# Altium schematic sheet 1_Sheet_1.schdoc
size 599 x 426 mm; Name: A_A2; Symbol: A_A2; Device: A_A2; @Project Name: OAE board 0.2; REV: 1.0; Date: 2023-09-23; Sheet: 1/1; Draw By: intercipere; Company: Your Company; Convert to PCB: yes; Add into BOM: yes; @Page No: 1; @Page Count: 1; @Schematic Name: OAE board 0.4; @Board Name: OAE board 0.4; @Update Date: 2025-04-07; @Create Time: 11:09:19; @Update Time: 13:09:20; @Page Name: Sheet_1; @Create Date: 2025-04-07
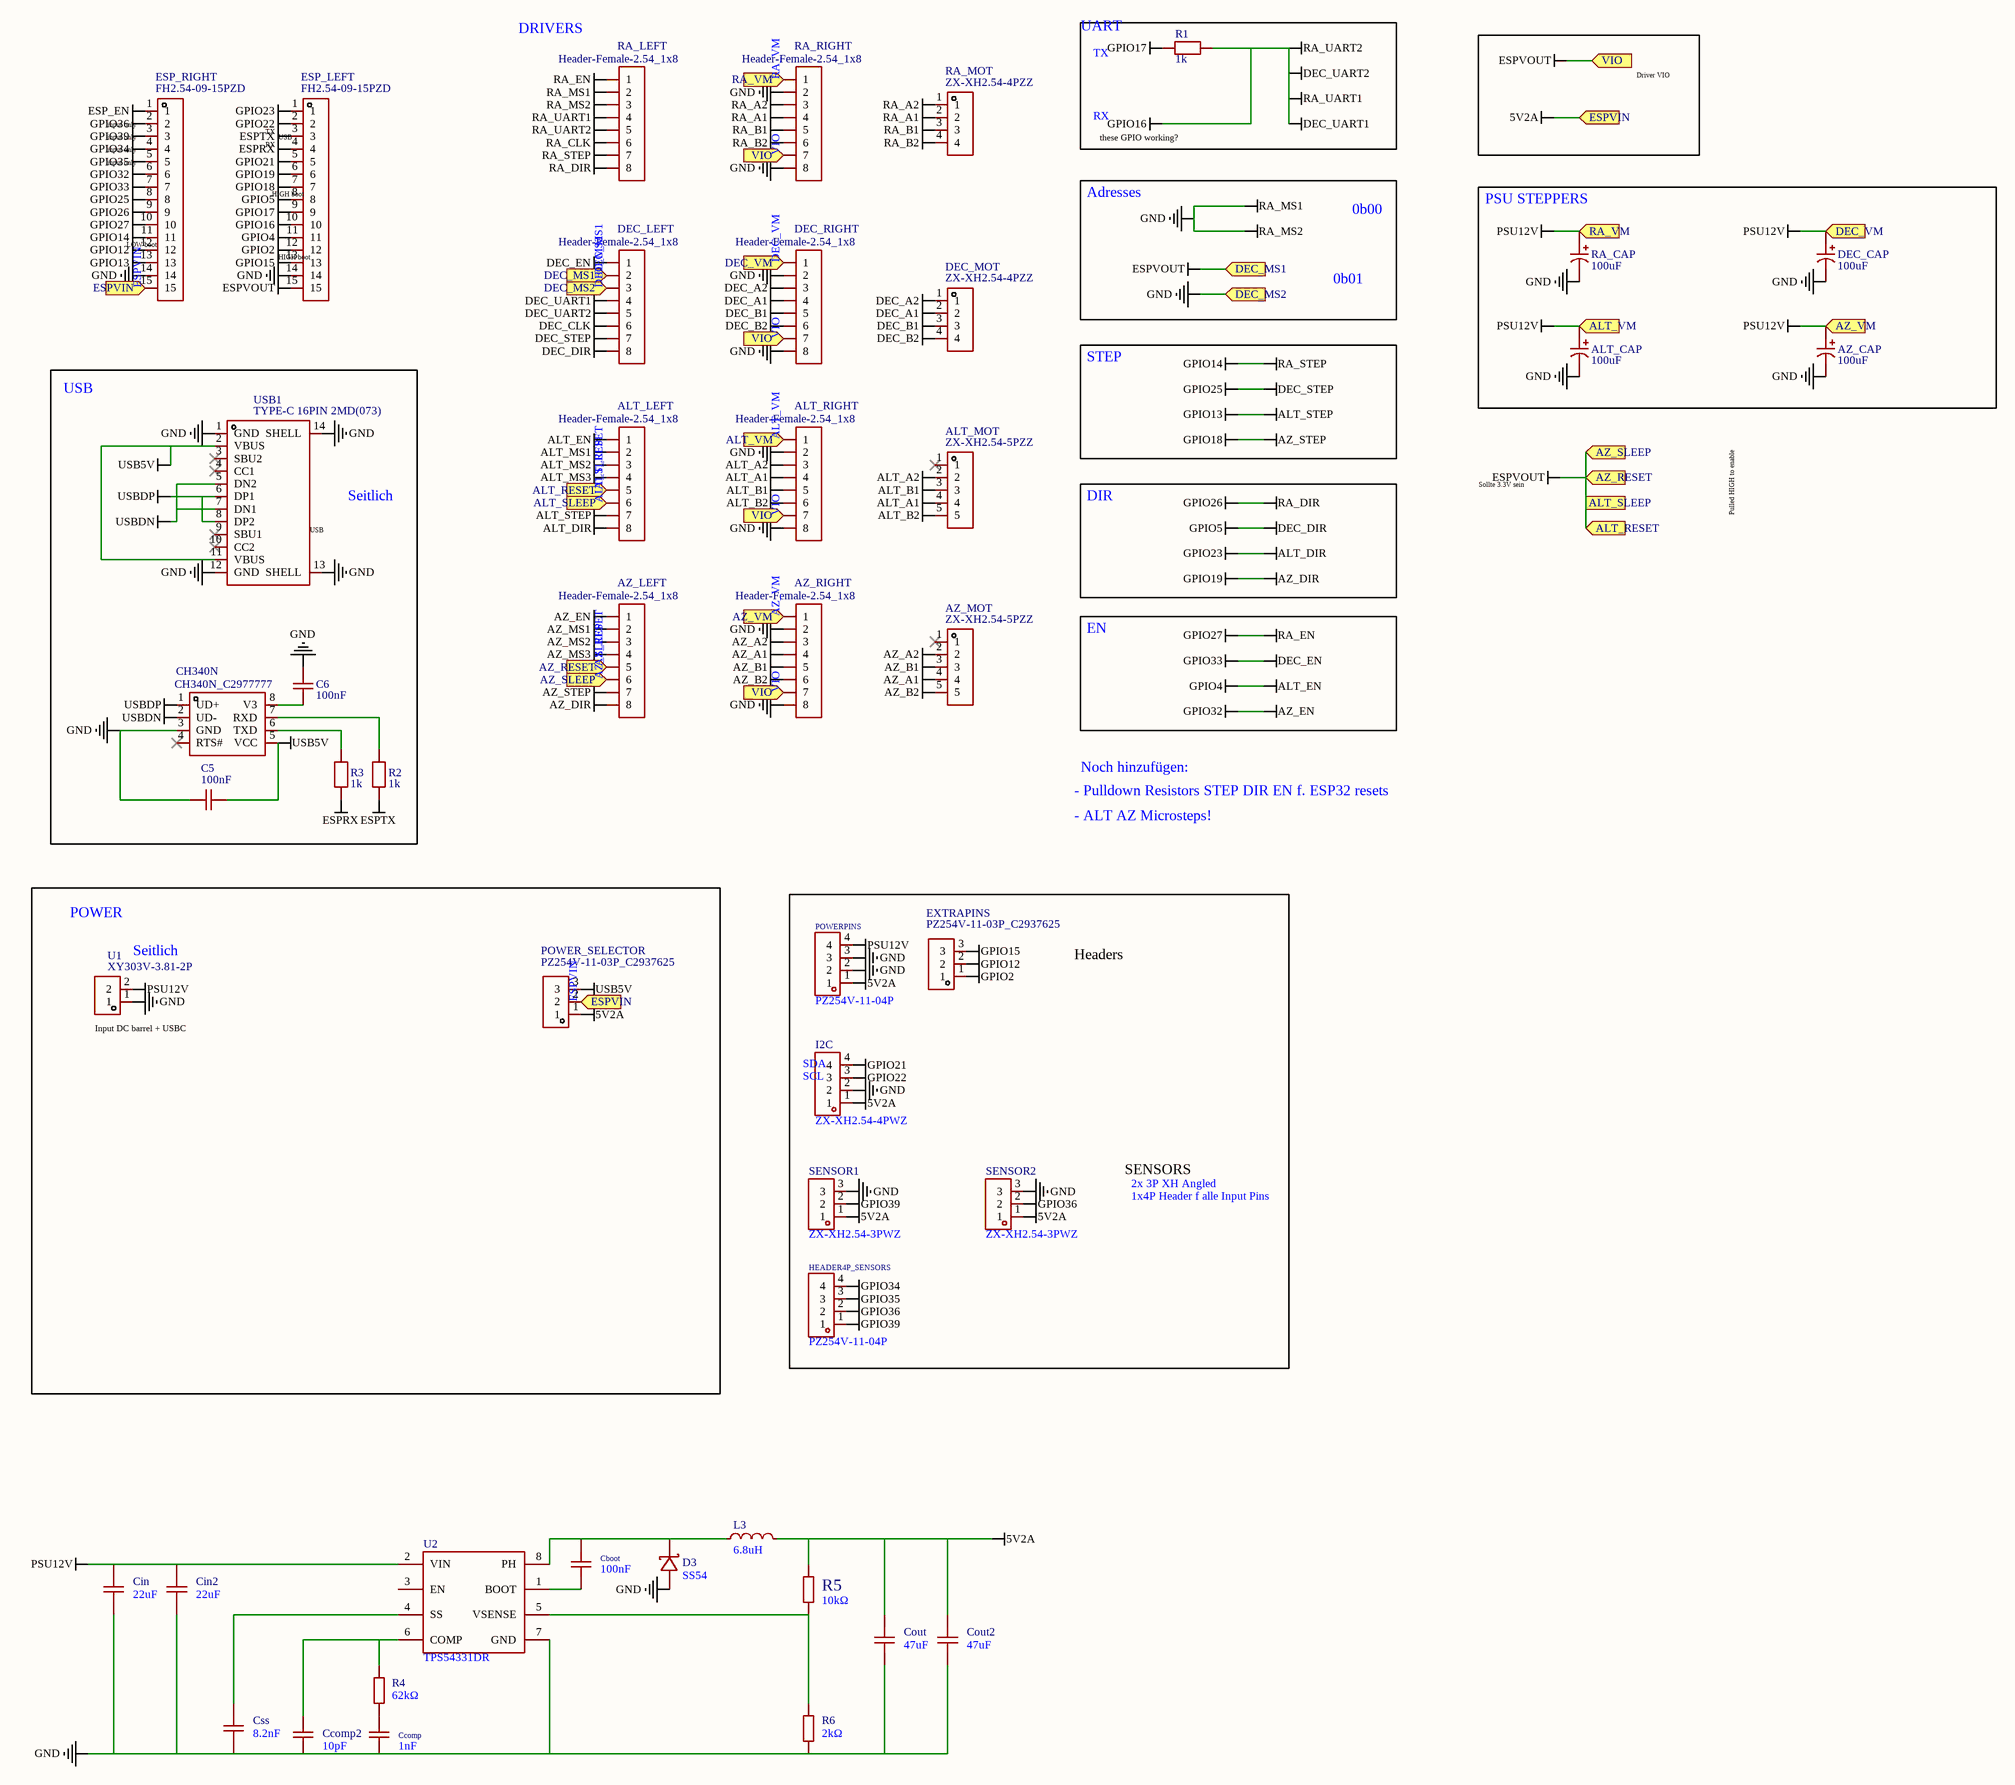
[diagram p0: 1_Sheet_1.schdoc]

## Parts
ALT_CAP  100uF  [CAP-SMD_BD6.3-L6.6-W6.6-LS7.4-FD]
ALT_LEFT  Header-Female-2.54_1x8  [HDR-TH_8P-P2.54-V-F-1]
ALT_MOT  ZX-XH2.54-5PZZ  [CONN-TH_5P-P2.50_ZX-XH2.54-5PZZ]
ALT_RIGHT  Header-Female-2.54_1x8  [HDR-TH_8P-P2.54-V-F-1]
AZ_CAP  100uF  [CAP-SMD_BD6.3-L6.6-W6.6-LS7.4-FD]
AZ_LEFT  Header-Female-2.54_1x8  [HDR-TH_8P-P2.54-V-F-1]
AZ_MOT  ZX-XH2.54-5PZZ  [CONN-TH_5P-P2.50_ZX-XH2.54-5PZZ]
AZ_RIGHT  Header-Female-2.54_1x8  [HDR-TH_8P-P2.54-V-F-1]
C5  100nF  [C0402]
C6  100nF  [C0402]
Cboot  100nF  [C0603]
Ccomp  1nF  [C0603]
Ccomp2  10pF  [C0603]
CH340N  CH340N_C2977777  [SOP-8_L4.9-W3.9-P1.27-LS6.0-BL]
Cin  22uF  [C0805]
Cin2  22uF  [C0805]
Cout  47uF  [C1206]
Cout2  47uF  [C1206]
Css  8.2nF  [C0603]
D3  SS54  [SMA_L4.4-W2.8-LS5.4-R-RD]
DEC_CAP  100uF  [CAP-SMD_BD6.3-L6.6-W6.6-LS7.4-FD]
DEC_LEFT  Header-Female-2.54_1x8  [HDR-TH_8P-P2.54-V-F-1]
DEC_MOT  ZX-XH2.54-4PZZ  [CONN-TH_4P-P2.50_4PIN]
DEC_RIGHT  Header-Female-2.54_1x8  [HDR-TH_8P-P2.54-V-F-1]
ESP_LEFT  FH2.54-09-15PZD  [HDR-TH_15P-P2.54-V-F-1]
ESP_RIGHT  FH2.54-09-15PZD  [HDR-TH_15P-P2.54-V-F-1]
EXTRAPINS  PZ254V-11-03P_C2937625  [HDR-TH_3P-P2.54-V-M]
HEADER4P_SENSORS  PZ254V-11-04P  [HDR-TH_4P-P2.54-V-M]
I2C  ZX-XH2.54-4PWZ  [CONN-TH_4P-P2.50_ZX-XH2.54-4PWZ]
L3  6.8uH  [IND-SMD_L2.0-W1.3]
POWER_SELECTOR  PZ254V-11-03P_C2937625  [HDR-TH_3P-P2.54-V-M]
POWERPINS  PZ254V-11-04P  [HDR-TH_4P-P2.54-V-M]
R1  1k  [R0603]
R2  1k  [R0603]
R3  1k  [R0603]
R4  62kΩ  [R0805]
R5  10kΩ  [R0603]
R6  2kΩ  [R0603]
RA_CAP  100uF  [CAP-SMD_BD6.3-L6.6-W6.6-LS7.4-FD]
RA_LEFT  Header-Female-2.54_1x8  [HDR-TH_8P-P2.54-V-F-1]
RA_MOT  ZX-XH2.54-4PZZ  [CONN-TH_4P-P2.50_4PIN]
RA_RIGHT  Header-Female-2.54_1x8  [HDR-TH_8P-P2.54-V-F-1]
SENSOR1  ZX-XH2.54-3PWZ  [HDR-TH_3P-P2.50_ZX-XH2.54-3PWZ]
SENSOR2  ZX-XH2.54-3PWZ  [HDR-TH_3P-P2.50_ZX-XH2.54-3PWZ]
U1  XY303V-3.81-2P  [CONN-TH_XY303V-3.81-2P]
U2  TPS54331DR  [SOIC-8_L5.0-W4.0-P1.27-LS6.0-BL]
USB1  TYPE-C 16PIN 2MD(073)  [USB-C-SMD_TYPE-C-6PIN-2MD-073]

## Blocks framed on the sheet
UART: R1
PSU STEPPERS: ALT_CAP AZ_CAP DEC_CAP RA_CAP

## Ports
ALT_RESET (in), ALT_SLEEP (in), ALT_VM (in), AZ_RESET (in), AZ_SLEEP (in), AZ_VM (in), DEC_MS1 (in), DEC_MS2 (in), DEC_VM (in), ESPVIN (in), RA_VM (in), VIO (in)

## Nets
ALT_A1: ALT_MOT.4 ALT_RIGHT.4
ALT_A2: ALT_MOT.2 ALT_RIGHT.3
ALT_B1: ALT_MOT.3 ALT_RIGHT.5
ALT_B2: ALT_MOT.5 ALT_RIGHT.6
ALT_DIR: ALT_LEFT.8 ESP_LEFT.1  [also labelled GPIO23]
ALT_EN: ALT_LEFT.1 ESP_LEFT.11  [also labelled GPIO4]
ALT_MS1: ALT_LEFT.2
ALT_MS2: ALT_LEFT.3
ALT_MS3: ALT_LEFT.4
ALT_RESET: ALT_LEFT.5 ALT_LEFT.6 ALT_RIGHT.7 AZ_LEFT.5 AZ_LEFT.6 AZ_RIGHT.7 DEC_LEFT.2 DEC_RIGHT.7 ESP_LEFT.15 RA_RIGHT.7 ; port ALT_RESET, port ALT_SLEEP, port AZ_RESET, port AZ_SLEEP, port DEC_MS1, port VIO  [also labelled ALT_SLEEP, AZ_RESET, AZ_SLEEP, DEC_MS1, ESPVOUT, VIO]
ALT_STEP: ALT_LEFT.7 ESP_RIGHT.13  [also labelled GPIO13]
ALT_VM: ALT_CAP.1 ALT_RIGHT.1 AZ_CAP.1 AZ_RIGHT.1 Cin.2 Cin2.2 DEC_CAP.1 DEC_RIGHT.1 POWERPINS.4 RA_CAP.1 RA_RIGHT.1 U1.2 U2.2(VIN) ; port RA_VM, port DEC_VM, port ALT_VM, port AZ_VM  [also labelled AZ_VM, DEC_VM, PSU12V, RA_VM]
AZ_A1: AZ_MOT.4 AZ_RIGHT.4
AZ_A2: AZ_MOT.2 AZ_RIGHT.3
AZ_B1: AZ_MOT.3 AZ_RIGHT.5
AZ_B2: AZ_MOT.5 AZ_RIGHT.6
AZ_DIR: AZ_LEFT.8 ESP_LEFT.6  [also labelled GPIO19]
AZ_EN: AZ_LEFT.1 ESP_RIGHT.6  [also labelled GPIO32]
AZ_MS1: AZ_LEFT.2
AZ_MS2: AZ_LEFT.3
AZ_MS3: AZ_LEFT.4
AZ_STEP: AZ_LEFT.7 ESP_LEFT.7  [also labelled GPIO18]
DEC_A1: DEC_MOT.2 DEC_RIGHT.4
DEC_A2: DEC_MOT.1 DEC_RIGHT.3
DEC_B1: DEC_MOT.3 DEC_RIGHT.5
DEC_B2: DEC_MOT.4 DEC_RIGHT.6
DEC_CLK: DEC_LEFT.6
DEC_DIR: DEC_LEFT.8 ESP_LEFT.8  [also labelled GPIO5]
DEC_EN: DEC_LEFT.1 ESP_RIGHT.7  [also labelled GPIO33]
DEC_MS2: ALT_CAP.2 ALT_RIGHT.2 ALT_RIGHT.8 AZ_CAP.2 AZ_RIGHT.2 AZ_RIGHT.8 C5.1 C6.2 Ccomp.1 Ccomp2.1 CH340N.3(GND) Cin.1 Cin2.1 Cout.1 Cout2.1 Css.2 D3.1(A) DEC_CAP.2 DEC_LEFT.3 DEC_RIGHT.2 DEC_RIGHT.8 ESP_LEFT.14 ESP_RIGHT.14 I2C.2 POWERPINS.2 POWERPINS.3 R6.1 RA_CAP.2 RA_LEFT.2 RA_LEFT.3 RA_RIGHT.2 RA_RIGHT.8 SENSOR1.3 SENSOR2.3 U1.1 U2.7(GND) USB1.1(GND) USB1.12(GND) USB1.13(SHELL) USB1.14(SHELL) ; port DEC_MS2  [also labelled GND, RA_MS1, RA_MS2]
DEC_STEP: DEC_LEFT.7 ESP_RIGHT.8  [also labelled GPIO25]
DEC_UART1: DEC_LEFT.4 DEC_LEFT.5 ESP_LEFT.10 R1.1 RA_LEFT.4 RA_LEFT.5  [also labelled DEC_UART2, GPIO16, RA_UART1, RA_UART2]
ESP_EN: ESP_RIGHT.1
ESPRX: ESP_LEFT.4 R3.1
ESPTX: ESP_LEFT.3 R2.1
ESPVIN: Cout.2 Cout2.2 ESP_RIGHT.15 I2C.1 L3.2 POWER_SELECTOR.1 POWER_SELECTOR.2 POWERPINS.1 R5.2 SENSOR1.1 SENSOR2.1 ; port ESPVIN  [also labelled 5V2A]
GPIO2: ESP_LEFT.12 EXTRAPINS.1
GPIO12: ESP_RIGHT.12 EXTRAPINS.2
GPIO14: ESP_RIGHT.11 RA_LEFT.7  [also labelled RA_STEP]
GPIO15: ESP_LEFT.13 EXTRAPINS.3
GPIO17: ESP_LEFT.9 R1.2
GPIO21: ESP_LEFT.5 I2C.4
GPIO22: ESP_LEFT.2 I2C.3
GPIO26: ESP_RIGHT.9 RA_LEFT.8  [also labelled RA_DIR]
GPIO27: ESP_RIGHT.10 RA_LEFT.1  [also labelled RA_EN]
GPIO34: ESP_RIGHT.4 HEADER4P_SENSORS.4
GPIO35: ESP_RIGHT.5 HEADER4P_SENSORS.3
GPIO36: ESP_RIGHT.2 HEADER4P_SENSORS.2 SENSOR2.2
GPIO39: ESP_RIGHT.3 HEADER4P_SENSORS.1 SENSOR1.2
RA_A1: RA_MOT.2 RA_RIGHT.4
RA_A2: RA_MOT.1 RA_RIGHT.3
RA_B1: RA_MOT.3 RA_RIGHT.5
RA_B2: RA_MOT.4 RA_RIGHT.6
RA_CLK: RA_LEFT.6
USB5V: C5.2 CH340N.5(VCC) POWER_SELECTOR.3 USB1.2(VBUS) USB1.11(VBUS)
USBDN: CH340N.2(UD-) USB1.5(DN2) USB1.7(DN1)
USBDP: CH340N.1(UD+) USB1.6(DP1) USB1.8(DP2)
NetC6_1: C6.1 CH340N.8(V3)
NetCboot_1: Cboot.1 U2.1(BOOT)
NetCboot_2: Cboot.2 D3.2(K) L3.1 U2.8(PH)
NetCcomp2_2: Ccomp2.2 R4.2 U2.6(COMP)
NetCcomp_2: Ccomp.2 R4.1
NetCH340N_6: CH340N.6(TXD) R3.2
NetCH340N_7: CH340N.7(RXD) R2.2
NetCss_1: Css.1 U2.4(SS)
NetR5_1: R5.1 R6.2 U2.5(VSENSE)

Not connected (* = marked no-connect by the designer): ALT_MOT 1*; AZ_MOT 1*; CH340N 4(RTS#)*; U2 3(EN); USB1 3(SBU2)* 4(CC1)* 9(SBU1)* 10(CC2)*

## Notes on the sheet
- DRIVERS
- TX
- (near ESP_RIGHT) input only
- RX
- Driver VIO
- (near ESP_LEFT) TX
- (near ESP_LEFT) RX
- (near ESP_LEFT) USB
- these GPIO working?
- (near ESP_RIGHT) LOW boot
- (near ESP_LEFT) HIGH boot
- Adresses
- 0b00
- 0b01
- STEP
- USB
- (near USB1) Seitlich
- DIR
- Sollte 3.3V sein
- Pulled HIGH to enable
- (near USB1) USB
- EN
- - Pulldown Resistors STEP DIR EN f. ESP32 resets
- - ALT AZ Microsteps!
- Noch hinzufügen:
- POWER
- (near U1) Seitlich
- Headers
- (near U1) Input DC barrel + USBC
- (near I2C) SDA
- (near I2C) SCL
- SENSORS
- 2x 3P XH Angled
- 1x4P Header f alle Input Pins

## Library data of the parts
ALT_CAP AZ_CAP DEC_CAP RA_CAP = 100uF: Manufacturer: KNSCHA(科尼盛); Manufacturer Part: RVE100UF35V67RV0072; Convert to PCB: yes
ALT_LEFT ALT_RIGHT AZ_LEFT AZ_RIGHT DEC_LEFT DEC_RIGHT RA_LEFT RA_RIGHT = Header-Female-2.54_1x8: Manufacturer: BOOMELE(博穆精密); Convert to PCB: yes
ALT_MOT AZ_MOT = ZX-XH2.54-5PZZ: Manufacturer: Megastar(兆星); Convert to PCB: yes
C5 C6 = 100nF: Manufacturer Part: CL05B104KO5NNNC; Manufacturer: SAMSUNG(三星); Convert to PCB: yes
Cboot = CC0603KRX7R9BB104: Manufacturer: YAGEO(国巨); Add into BOM: yes; Tolerance: ±10%
Ccomp = CL10B102KB8NNNC: Manufacturer: SAMSUNG(三星); Add into BOM: yes; Tolerance: ±10%
Ccomp2 = CL10C100JB8NNNC: Manufacturer: SAMSUNG(三星); Add into BOM: yes; Tolerance: ±5%
CH340N = CH340N_C2977777: Manufacturer: WCH(南京沁恒); Manufacturer Part: CH340N; Convert to PCB: yes
Cin Cin2 = CL21A226MAQNNNE: Manufacturer: SAMSUNG(三星); Add into BOM: yes; Tolerance: ±20%
Cout Cout2 = CL31A476MPHNNNE: Manufacturer: SAMSUNG(三星); Add into BOM: yes; Tolerance: ±20%
Css = 0603B822K500NT: Manufacturer: FH(风华); Add into BOM: yes; Tolerance: ±10%
D3 = SS54_C22452: Manufacturer: MDD(辰达半导体); Add into BOM: yes; Diode Configuration: Independent Type; Forward Voltage (Vf@If): 550mV@5A; Reverse Voltage (Vr): 40V; Rectified Current: 5A; Reverse Leakage Current (Ir): 1mA@40V
DEC_MOT RA_MOT = ZX-XH2.54-4PZZ: Manufacturer: Megastar(兆星); Convert to PCB: yes
ESP_LEFT ESP_RIGHT = FH2.54-09-15PZD: Manufacturer: XUNPU(讯普); Manufacturer Part: ZX-PM2.54-1-15PY; Convert to PCB: yes
EXTRAPINS POWER_SELECTOR = PZ254V-11-03P_C2937625: Manufacturer: XFCN(兴飞); Convert to PCB: yes
HEADER4P_SENSORS POWERPINS = PZ254V-11-04P: Manufacturer: XFCN(兴飞); Symbol: PZ254V-11-04P_C2691448; Add into BOM: yes; Pin Structure: 1x4P; Pitch: 2.54mm; Circluar Pins/Square Pins: Square Pins; Current Rating (Max): 3A; Voltage Rating (Max): 250V
I2C = ZX-XH2.54-4PWZ: Manufacturer: Megastar(兆星); Add into BOM: yes; Pins Structure: 1x4P; Pitch: 2.5mm; Reference Series: XH; Number of PINs Per Row: 4; Rated Current: 3A; Rated Voltage (Max): 250V; Plastic Material: PA66; Flame Retardant Rating: UL94V-0; Z-Height of the Board: 5.9mm; X-Length of Bottom Edge on Board (Spacing Line): 12.5mm; Y-Width of Bottom Edge on Board: 7.32mm
L3 = MLZ2012N6R8LT000: Manufacturer: TDK; Add into BOM: yes; Tolerance: ±20%; Saturation Current (Isat): 110mA
R1-R3 = 1k: Convert to PCB: yes
R4 = 0805W8F6202T5E: Manufacturer: UNI-ROYAL(厚声); Add into BOM: yes; Tolerance: ±1%; Temperature Coefficient: ±100ppm/℃
R5 = 0603WAF1002T5E: Manufacturer: UNI-ROYAL(厚声); Add into BOM: yes; Tolerance: ±1%; Temperature Coefficient: ±100ppm/℃
R6 = 0603WAF2001T5E: Manufacturer: UNI-ROYAL(厚声); Add into BOM: yes; Tolerance: ±1%; Temperature Coefficient: ±100ppm/℃
SENSOR1 SENSOR2 = ZX-XH2.54-3PWZ: Manufacturer: Megastar(兆星); Add into BOM: yes; Pins Structure: 1x3P; Pitch: 2.5mm; Reference Series: XH; Number of PINs Per Row: 3; Rated Current: 3A; Rated Voltage (Max): 250V; Plastic Material: PA66; Flame Retardant Rating: UL94V-0; Z-Height of the Board: 5.9mm; X-Length of Bottom Edge on Board (Spacing Line): 10mm; Y-Width of Bottom Edge on Board: 7.32mm
U1 = XY303V-3.81-2P: Manufacturer: XINLAIYA(新莱亚); Convert to PCB: yes
U2 = TPS54331DR: Manufacturer: TI(德州仪器); Add into BOM: yes; Function: Step-down type; Output Type: Adjustable; Input Voltage: 3.5V~28V; Output Current: 3A; Switching Frequency: 570kHz; Synchronous Rectification: No; Number of Outputs: 1; Topology: Step-down; Quiescent Current (Iq): 1mA; Switch tube (built-in/external): Built-in
USB1 = TYPE-C 16PIN 2MD(073): Manufacturer: SHOU HAN(首韩); Convert to PCB: yes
